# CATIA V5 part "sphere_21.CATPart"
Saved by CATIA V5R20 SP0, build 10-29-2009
Part number: sphère_21
Bounding box of the stored display mesh (mm): x -44.988 to 44.988, y -9.154 to 50, z -44.995 to 44.995
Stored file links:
  C:\Users\Thinkmotion2\Desktop\Pack 2\CFAO_2010\abaussand\CFAO_abaussand_Catia_V5R20\sphere_21.CATPart
  C:\Users\Thinkmotion2\Desktop\Pack 2\CFAO_2010\abaussand\CFAO_abaussand_Catia_V5R20\abaussand_2.CATProduct
  C:\Users\Thinkmotion2\Desktop\Pack 2\CFAO_2010\abaussand\CFAO_abaussand_Catia_V5R20\support_17.CATPart
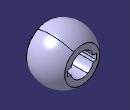
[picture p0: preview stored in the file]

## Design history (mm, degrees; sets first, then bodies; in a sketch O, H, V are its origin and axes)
Body1 (main body)
  Sketch1 on yz-plane, origin (0, 0, 0), H (0, 1, 0), V (0, 0, 1)
    point P1 (0, 30)
    line L1 (0, 30) -> (-9.1535, 30)
    line L2 (-9.1535, 30) -> (-9.1535, 37)
    line L3 (0, 30) -> (0, 20)
    line L4 (0, 20) -> (50, 20)
    line L5 (50, 20) -> (50, 30)
    arc A1 centre (16.459, 0) radius 45 from (50, 30) to (-9.1535, 37) ccw
    point P7 (16.459, 0)
    distance L4 H = 20
    length L3 = 10
    length L2 = 7
    length L5 = 10
    radius A1 = 45
    length L4 = 50
    coincidence: P1 V, P7 H
    horizontal: L1 H, L4 H
    vertical: L2 V, L3 V, L5 V
  Shaft1: profile Sketch1, axis Sketch1.H, angle 360
  Sketch2 on zx-plane, origin (0, 0, 0), H (-1, 0, 0), V (0, 0, 1)
    line L1 (25, 5) -> (-25, 5)
    line L2 (-25, 5) -> (-25, -5)
    line L3 (-25, -5) -> (25, -5)
    line L4 (25, -5) -> (25, 5)
    length L4 = 10
    distance L3 H = 5
    length L1 = 50
    distance V L4 = 25
    horizontal: L1 H, L3 H
    vertical: L2 V, L4 V
  Pocket1: profile Sketch2, direction (0, -1, 0), through (limit type 3)
  Point1: type OnPlane, Support xy-plane, H 0, V 23.077, Direction (1, 0, 0)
